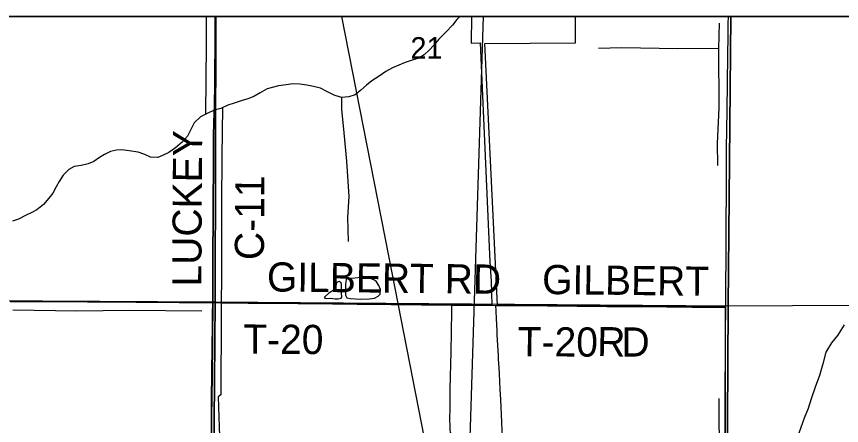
# Model space of a CAD drawing. Extents: x -8.3 to 42.1, y 0 to 22.
# Drawn here: x 3.551 to 5.158, y 20.104 to 20.9 of the extents above; entities that cross this region are included whole.
import ezdxf

# ---------------------------------------------------------------- set-up
doc = ezdxf.new("R2010")
doc.units = 0
for name, color, linetype in [('Default', 7, 'Continuous'), ('GM_X_City_Street', 7, 'Continuous'), ('GM_X_Corporation', 7, 'Continuous'), ('GM_X_County_Road', 7, 'Continuous'), ('GM_X_County_Road_Text', 7, 'Continuous'), ('GM_X_Major_River', 7, 'Continuous'), ('GM_X_Minor_Lake', 7, 'Continuous'), ('GM_X_Minor_River', 7, 'Continuous'), ('GM_X_Rail_Line', 7, 'Continuous'), ('GM_X_Section', 7, 'Continuous'), ('GM_X_Section_Text', 7, 'Continuous'), ('GM_X_State_Route', 7, 'Continuous'), ('GM_X_Township_Road', 7, 'Continuous'), ('GM_X_Township_Road_Text', 7, 'Continuous'), ('SH_Cut_Line', 7, 'Continuous'), ('SH_Data', 7, 'Continuous')]:
    doc.layers.add(name, color=color, linetype=linetype)

msp = doc.modelspace()

# ---------------------------------------------------------------- linework, layer by layer
at = {"layer": 'Default'}
for points in [[(3.9394, 20.9), (2.9318, 20.9), (2.9276, 20.3504), (3.938, 20.3445)], [(4.9425, 20.9), (3.9394, 20.9), (3.938, 20.3445), (4.9373, 20.3372)], [(5.9435, 20.9), (4.9425, 20.9), (4.9373, 20.3372), (5.9413, 20.342)]]:
    msp.add_lwpolyline(points, close=True, dxfattribs=at)
at = {"layer": 'GM_X_City_Street'}
for points in [[(4.3991, 20.0825), (4.3981, 20.0851), (4.3975, 20.0868), (4.3969, 20.0889), (4.3962, 20.0914), (4.3957, 20.0952), (4.3956, 20.099), (4.3953, 20.1195), (4.3955, 20.1354), (4.3957, 20.1746), (4.3975, 20.2477), (4.3982, 20.2862), (4.3987, 20.3263), (4.3989, 20.3382)], [(4.4976, 20.0858), (4.4972, 20.0935), (4.4964, 20.1108), (4.4942, 20.1548), (4.4933, 20.174), (4.4916, 20.2056), (4.491, 20.2161), (4.49, 20.2335), (4.4896, 20.2403), (4.4891, 20.2502), (4.4875, 20.2806), (4.4871, 20.2892), (4.4858, 20.3115), (4.4853, 20.3274), (4.4849, 20.3379)]]:
    msp.add_lwpolyline(points, dxfattribs=at)
at = {"layer": 'GM_X_Corporation'}
msp.add_lwpolyline([(4.9315, 20.0835), (4.932, 20.3341), (4.6158, 20.3376), (4.6108, 20.3373), (4.4879, 20.3385), (4.463, 20.8476), (4.6399, 20.8485), (4.6396, 20.9), (4.4369, 20.9), (4.4366, 20.8483), (4.4538, 20.8486), (4.4732, 20.4226), (4.4752, 20.3853), (4.4769, 20.3386), (4.3986, 20.3388), (3.9333, 20.3442), (3.9317, 20.2038), (3.9305, 20.0825)], dxfattribs=at)
at = {"layer": 'GM_X_County_Road'}
for points in [[(3.9336, 20.3437), (3.9335, 20.3619), (3.9337, 20.4104), (3.9338, 20.4434), (3.9341, 20.4987), (3.9345, 20.5366), (3.9347, 20.6094), (3.9347, 20.6517), (3.9351, 20.6658), (3.9356, 20.6938), (3.9366, 20.7273), (3.9374, 20.7678), (3.9377, 20.7964), (3.9382, 20.838), (3.9383, 20.8759), (3.9384, 20.9)], [(3.93, 20.0205), (3.93, 20.0235), (3.9303, 20.0471), (3.9307, 20.082), (3.9309, 20.1224), (3.9313, 20.1572), (3.9319, 20.2032), (3.9325, 20.2598), (3.9327, 20.2946), (3.9331, 20.3201), (3.9336, 20.3437)]]:
    msp.add_lwpolyline(points, dxfattribs=at)
at = {"layer": 'GM_X_Major_River'}
msp.add_lwpolyline([(4.4145, 20.9), (4.4083, 20.8944), (4.4, 20.8832), (4.388, 20.8702), (4.3736, 20.8561), (4.3638, 20.8442), (4.3549, 20.8342), (4.3448, 20.8257), (4.3344, 20.8191), (4.3215, 20.8149), (4.3081, 20.8103), (4.2955, 20.8056), (4.2832, 20.7999), (4.2702, 20.793), (4.2571, 20.7842), (4.2432, 20.775), (4.2324, 20.7665), (4.2219, 20.7566), (4.2103, 20.7477), (4.1986, 20.7437), (4.1837, 20.7427), (4.1694, 20.7468), (4.1556, 20.7544), (4.1429, 20.7607), (4.1297, 20.7641), (4.1165, 20.7667), (4.1029, 20.7685), (4.0889, 20.7689), (4.0764, 20.7673), (4.0616, 20.765), (4.0395, 20.7594), (4.0256, 20.7514), (4.0133, 20.7445), (4.0019, 20.7395), (3.9908, 20.7367), (3.9748, 20.7314), (3.9625, 20.7275), (3.9491, 20.721), (3.9358, 20.7179), (3.9224, 20.711), (3.9093, 20.7045), (3.8973, 20.6931), (3.891, 20.6814), (3.8842, 20.6672), (3.874, 20.6553), (3.8605, 20.6446), (3.8478, 20.6354), (3.8351, 20.6297), (3.8265, 20.6258), (3.8123, 20.6264), (3.8007, 20.6313), (3.7883, 20.6361), (3.7702, 20.6388), (3.7563, 20.6403), (3.746, 20.6402), (3.7342, 20.6374), (3.7227, 20.6312), (3.7127, 20.6254), (3.7015, 20.6177), (3.6908, 20.613), (3.6771, 20.6103), (3.6634, 20.608), (3.6527, 20.6022), (3.6422, 20.5911), (3.6343, 20.5787), (3.6284, 20.5686), (3.6216, 20.5563), (3.6142, 20.5466), (3.6037, 20.5343), (3.5905, 20.524), (3.5809, 20.5185), (3.5683, 20.5128), (3.5549, 20.5055), (3.5432, 20.5019)], dxfattribs=at)
at = {"layer": 'GM_X_Minor_Lake'}
for p, q in [((4.1837, 20.362), (4.1838, 20.3787)), ((4.1921, 20.38), (4.1916, 20.3577))]:
    msp.add_line(p, q, dxfattribs=at)
for points in [[(4.1916, 20.3577), (4.1941, 20.3523), (4.2013, 20.351), (4.2202, 20.3498), (4.238, 20.3508), (4.2482, 20.3517), (4.2555, 20.3557), (4.259, 20.3594), (4.26, 20.3689), (4.2564, 20.3766), (4.2521, 20.3835), (4.2483, 20.3867), (4.2375, 20.3915), (4.2223, 20.3922), (4.2098, 20.391), (4.2011, 20.3904), (4.1935, 20.3914), (4.1921, 20.38)], [(4.1838, 20.3787), (4.1835, 20.3818), (4.1797, 20.3841), (4.1744, 20.3824), (4.1723, 20.3729), (4.1676, 20.367), (4.1591, 20.3615), (4.1514, 20.3548), (4.1502, 20.3526), (4.1539, 20.3514), (4.1627, 20.3519), (4.1717, 20.3509), (4.1774, 20.3504), (4.1831, 20.3518), (4.1847, 20.3537), (4.1837, 20.362)]]:
    msp.add_lwpolyline(points, dxfattribs=at)
at = {"layer": 'GM_X_Minor_River'}
for points in [[(3.92, 20.7099), (3.9208, 20.8454), (3.9208, 20.9)], [(4.9193, 20.8869), (4.9181, 20.838), (4.919, 20.7226), (4.9154, 20.6532), (4.9162, 20.61)], [(4.9181, 20.838), (4.8393, 20.8369), (4.7303, 20.8388), (4.6844, 20.8376)], [(4.1837, 20.7427), (4.1843, 20.7195), (4.1884, 20.6735), (4.1935, 20.6187), (4.1986, 20.5495), (4.1957, 20.5086), (4.1968, 20.4623)], [(3.9525, 20.7227), (3.951, 20.6276), (3.9502, 20.535), (3.9503, 20.417), (3.9494, 20.3191), (3.9493, 20.1639), (3.9439, 20.1599), (3.9459, 20.1014), (3.9497, 19.9973), (3.9492, 19.9161), (3.9445, 19.846), (3.9466, 19.7959), (3.9445, 19.7268), (3.9428, 19.6275)], [(3.5439, 20.329), (3.6686, 20.3274), (3.7712, 20.3284), (3.9117, 20.3272)], [(5.163, 20.3), (5.15, 20.2791), (5.1383, 20.2649), (5.1272, 20.2466), (5.1214, 20.224), (5.1151, 20.2014), (5.1062, 20.1788), (5.0989, 20.1558), (5.0927, 20.1374), (5.0849, 20.1185), (5.0786, 20.1), (5.0745, 20.0889), (5.0705, 20.0769), (5.0638, 20.0698), (5.0607, 20.0691), (5.0271, 20.0654), (4.9955, 20.0642), (4.9606, 20.0632), (4.936, 20.063), (4.9254, 20.0661), (4.9218, 20.0709), (4.921, 20.0827), (4.9198, 20.0995), (4.9198, 20.1567)]]:
    msp.add_lwpolyline(points, dxfattribs=at)
at = {"layer": 'GM_X_Rail_Line'}
for points in [[(4.1842, 20.9), (4.2824, 20.3978), (4.5315, 19.127), (4.6541, 18.5101), (4.7015, 18.2399), (4.7193, 18.1628), (4.7437, 18.1035), (4.7782, 18.045), (4.9031, 17.884), (5.1089, 17.6286), (5.1497, 17.5693), (5.1874, 17.5157), (5.2262, 17.4447), (5.2601, 17.3769), (5.294, 17.2671), (5.315, 17.167), (5.3312, 17.0685), (5.3428, 16.9248)], [(4.4602, 20.9), (4.4279, 19.896), (4.4279, 19.7141), (4.5329, 19.1719), (4.7134, 18.2287), (4.7298, 18.1615), (4.7562, 18.1061), (4.7924, 18.0389), (4.852, 17.9646), (5.1115, 17.6457), (5.209, 17.5403), (5.4439, 17.3636), (5.6263, 17.2359), (5.6901, 17.1722)]]:
    msp.add_lwpolyline(points, dxfattribs=at)
at = {"layer": 'GM_X_Section'}
for points in [[(3.938, 20.3445), (3.9295, 19.335), (2.9241, 19.3359), (2.9276, 20.3504)], [(4.9373, 20.3372), (4.9315, 19.3303), (3.9295, 19.335), (3.938, 20.3445)], [(5.9413, 20.342), (5.9346, 19.331), (4.9315, 19.3303), (4.9373, 20.3372)]]:
    msp.add_lwpolyline(points, close=True, dxfattribs=at)
at = {"layer": 'GM_X_State_Route'}
for points in [[(3.5385, 20.3457), (3.6084, 20.3454), (3.6892, 20.3447), (3.7187, 20.3445), (3.784, 20.344), (3.8679, 20.3436), (3.9114, 20.3433), (3.9336, 20.3437)], [(3.9336, 20.3437), (3.9331, 20.3201), (3.9327, 20.2946), (3.9325, 20.2598), (3.9319, 20.2032), (3.9313, 20.1572), (3.9309, 20.1224), (3.9307, 20.082), (3.9303, 20.0471), (3.93, 20.0235), (3.93, 20.0205)]]:
    msp.add_lwpolyline(points, dxfattribs=at)
at = {"layer": 'GM_X_Township_Road'}
for p, q in [((4.4772, 20.338), (4.4849, 20.3379)), ((4.4849, 20.3379), (4.4881, 20.3379))]:
    msp.add_line(p, q, dxfattribs=at)
for points in [[(3.9305, 20.0825), (3.9306, 20.1229), (3.9311, 20.1578), (3.9317, 20.2038), (3.9323, 20.2604), (3.9325, 20.2952), (3.9329, 20.3207), (3.9333, 20.3442), (3.9333, 20.3625), (3.9335, 20.411), (3.9336, 20.4439), (3.9339, 20.4993), (3.9343, 20.5372), (3.9345, 20.6099), (3.9345, 20.6522), (3.9349, 20.6664), (3.9354, 20.6943), (3.9364, 20.7279), (3.9372, 20.7683), (3.9375, 20.7969), (3.938, 20.8386), (3.9381, 20.8765), (3.9382, 20.9), (2.1, 20.9)], [(7.9572, 20.9), (3.9382, 20.9), (3.9381, 20.8765), (3.938, 20.8386), (3.9375, 20.7969), (3.9372, 20.7683), (3.9364, 20.7279), (3.9354, 20.6943), (3.9349, 20.6664), (3.9345, 20.6522), (3.9345, 20.6099), (3.9343, 20.5372), (3.9339, 20.4993), (3.9336, 20.4439), (3.9335, 20.411), (3.9333, 20.3625), (3.9333, 20.3442), (3.9329, 20.3207), (3.9325, 20.2952), (3.9323, 20.2604), (3.9317, 20.2038), (3.9311, 20.1578), (3.9306, 20.1229), (3.9305, 20.0825)], [(4.9327, 20.3339), (4.9326, 20.3889), (4.933, 20.4192), (4.9331, 20.4459), (4.9331, 20.4801), (4.9334, 20.5069), (4.9337, 20.5503), (4.9339, 20.5854), (4.9341, 20.6432), (4.9352, 20.7172), (4.9365, 20.8242), (4.937, 20.8627), (4.9373, 20.8857), (4.9374, 20.9)], [(3.9336, 20.3437), (3.9428, 20.3433), (3.9498, 20.343), (3.9546, 20.3429), (4.002, 20.3423), (4.0989, 20.3414), (4.1666, 20.3412), (4.2145, 20.3405), (4.2424, 20.3402), (4.281, 20.3399), (4.3989, 20.3382)], [(4.3989, 20.3382), (4.4099, 20.3382), (4.4391, 20.3382), (4.4434, 20.3382), (4.4772, 20.338)], [(4.4881, 20.3379), (4.5034, 20.3379), (4.5855, 20.337), (4.6433, 20.3364), (4.7009, 20.3359), (4.7307, 20.3358), (4.8177, 20.3349), (4.8668, 20.3346), (4.9327, 20.3339)], [(4.9318, 20.083), (4.9321, 20.1052), (4.9321, 20.1263), (4.9319, 20.1555), (4.9322, 20.284), (4.9327, 20.3339)]]:
    msp.add_lwpolyline(points, dxfattribs=at)
at = {"layer": 'SH_Cut_Line'}
msp.add_lwpolyline([(7.9572, 20.9), (2.1, 20.9)], dxfattribs=at)
at = {"layer": 'SH_Data'}
msp.add_line((2.1, 20.9), (8.9, 20.9), dxfattribs=at)

# ---------------------------------------------------------------- texts
at = {"layer": 'GM_X_County_Road_Text'}
for s, rotation, p in [('LUCKEY', 89.6626, (3.911, 20.3744)), ('C-11', 89.6656, (4.0329, 20.4259))]:
    msp.add_text(s, height=0.05682, rotation=rotation, dxfattribs=at).set_placement(p)
at = {"layer": 'GM_X_Section_Text'}
msp.add_text('21', height=0.04186, rotation=0, dxfattribs=at).set_placement((4.3184, 20.818))
at = {"layer": 'GM_X_Township_Road_Text'}
for s, height, rotation, p in [('GILBERT RD', 0.05682, 359.4123, (4.0386, 20.365)), ('GILBERT', 0.05682, 359.3519, (4.5745, 20.36)), ('T-20', 0.05682, 359.6516, (3.9925, 20.244)), ('T-20', 0.05682, 359.6457, (4.5271, 20.239)), ('R', 0.0568, 358.8446, (4.6815, 20.2393)), ('D', 0.0568, 359.9664, (4.7294, 20.2383))]:
    msp.add_text(s, height=height, rotation=rotation, dxfattribs=at).set_placement(p)

doc.saveas('drawing.dxf')
